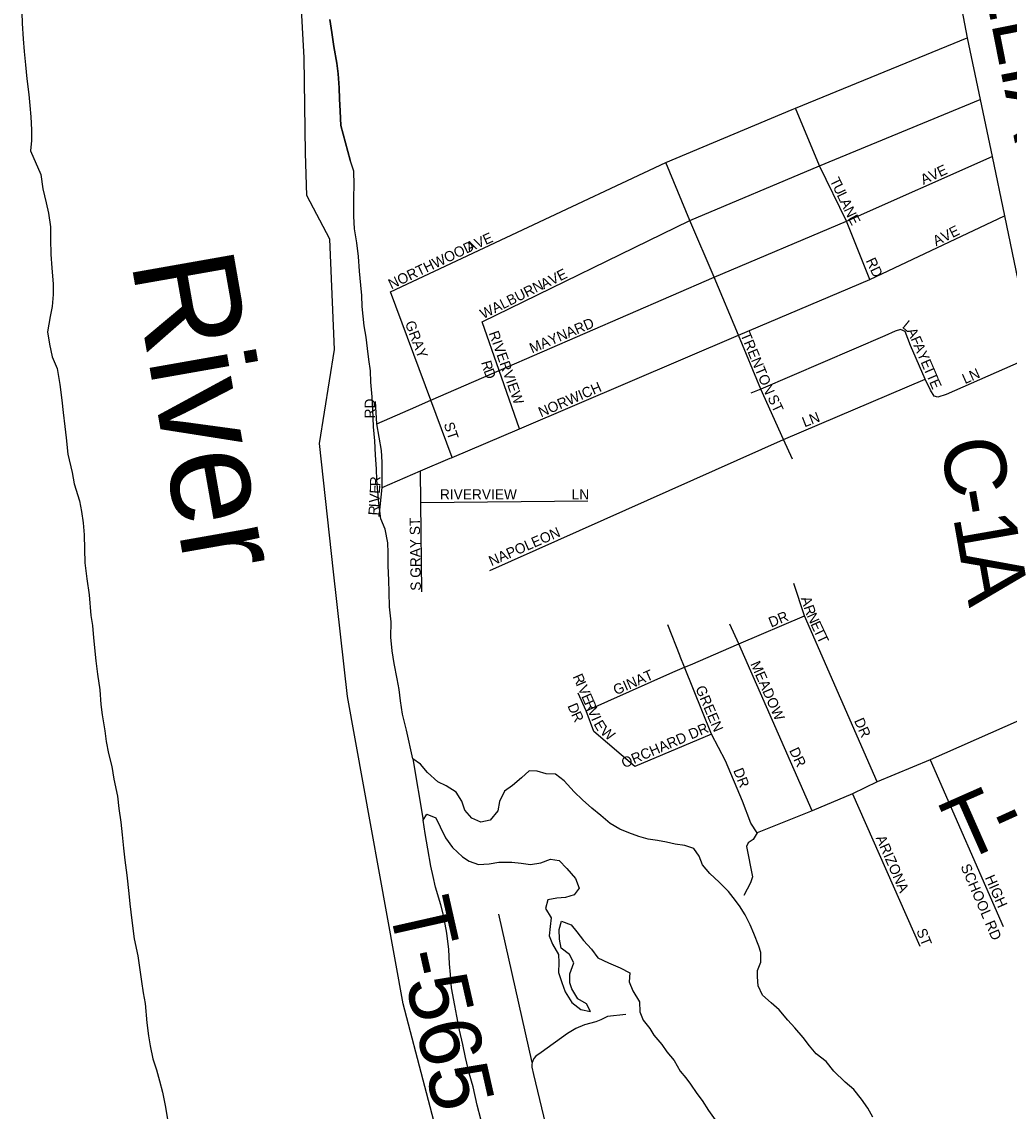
# Model space of a CAD drawing. Extents: x 1624196 to 2029251, y 146837 to 440034.
# Drawn here: x 1865322 to 1870139, y 223168 to 228483 of the extents above; entities that cross this region are included whole.
import ezdxf

# ---------------------------------------------------------------- set-up
doc = ezdxf.new("R2010")
doc.units = 0
for name, color, linetype in [('GM_X_County', 7, 'Continuous'), ('GM_X_County_Road', 7, 'Continuous'), ('GM_X_County_Road_Text', 7, 'Continuous'), ('GM_X_Major_River', 7, 'Continuous'), ('GM_X_Major_River_Text', 7, 'Continuous'), ('GM_X_Township', 7, 'Continuous'), ('GM_X_Township_Road', 7, 'Continuous'), ('GM_X_Township_Road_Text', 7, 'Continuous'), ('GM_X_Township_Subdivision', 7, 'Continuous'), ('GM_X_Township_Subdivision_Text', 7, 'Continuous')]:
    doc.layers.add(name, color=color, linetype=linetype)

msp = doc.modelspace()

# ---------------------------------------------------------------- linework, layer by layer
at = {"layer": 'GM_X_County'}
msp.add_lwpolyline([(1868956.8, 217512.7), (1868638.5, 218911.2), (1868232.1, 219758.7), (1868240.1, 219860.9), (1867949.8, 220532.1), (1867651.6, 221491.8), (1867393.3, 222884.3), (1867183.1, 223691.8), (1866910.8, 225190.5), (1866842.8, 225799.6), (1866774.7, 226424.7), (1866846.7, 226883.5), (1866824.7, 227422.5), (1866712.6, 227634.9), (1866705.8, 227842.5), (1866699.8, 228307.5), (1866657.8, 229078.2), (1866559.7, 229282.4), (1866457.7, 229772.9), (1866353.7, 230095.2), (1866417.7, 230521.6), (1866513.7, 230731.8), (1866563.7, 231274.4), (1866527.7, 232463.5)], dxfattribs=at)
at = {"layer": 'GM_X_County_Road'}
msp.add_lwpolyline([(1869763.2, 229303.8), (1869934.6, 228404.4), (1869997.4, 228103.3), (1870055.3, 227825.5), (1870115.7, 227535.9), (1870181.2, 227221.5), (1870231.5, 226954.2), (1870248.1, 226866.6), (1870354.7, 226302.8), (1870407.2, 226032.3), (1870452.8, 225744.5), (1870483.5, 225610.8), (1870514.2, 225428.5), (1870552.1, 225235.3), (1870606.6, 224963.7), (1870629.6, 224796.5), (1870709, 224246.7), (1870752.9, 223970.8), (1870773.8, 223690.7), (1870780.8, 223427.7), (1870792.7, 223044.3)], dxfattribs=at)
at = {"layer": 'GM_X_Major_River'}
msp.add_line((1867230.4, 224887.4), (1867280.4, 224588.1), dxfattribs=at)
for points in [[(1865321.9, 228528.4), (1865323.6, 228474.3), (1865329.2, 228400.2), (1865332.9, 228338.1), (1865340.6, 228272), (1865346.3, 228203.9), (1865355.9, 228127.8), (1865361.6, 228073.6), (1865365.3, 228019.6), (1865369, 227955.5), (1865368.8, 227903.4), (1865364.5, 227853.4)], [(1865321.9, 228528.4), (1865323.6, 228474.3), (1865329.2, 228400.2), (1865332.9, 228338.1), (1865340.6, 228272), (1865346.3, 228203.9), (1865355.9, 228127.8), (1865361.6, 228073.6), (1865365.3, 228019.6), (1865369, 227955.5), (1865368.8, 227903.4), (1865364.5, 227853.4)], [(1866924.3, 227807.2), (1866878.8, 227976.9), (1866875.1, 228047), (1866871.4, 228107.1), (1866869.7, 228161.2), (1866866, 228229.3), (1866858.3, 228281.4), (1866844.7, 228361.6), (1866835, 228429.7), (1866825.4, 228493.8)], [(1866825.4, 228493.8), (1866835, 228429.7), (1866844.7, 228361.6), (1866858.3, 228281.4), (1866866, 228229.3), (1866869.7, 228161.2), (1866871.4, 228107.1), (1866875.1, 228047), (1866878.8, 227976.9), (1866924.3, 227807.2)], [(1865364.5, 227853.4), (1865415.2, 227737.7), (1865424.8, 227667.5), (1865440.5, 227599.4), (1865452.2, 227549.2), (1865461.9, 227483), (1865461.6, 227422.9), (1865463.2, 227346.8), (1865468.9, 227282.7), (1865474.5, 227202.5), (1865474.3, 227152.4), (1865470, 227094.3), (1865459.7, 227044.3), (1865447.4, 226970.2), (1865457.1, 226910.1), (1865470.8, 226847.9), (1865494.5, 226791.7), (1865508.1, 226713.5), (1865517.7, 226637.3), (1865523.4, 226577.2), (1865531.1, 226509), (1865538.8, 226452.9), (1865546.4, 226372.7), (1865568, 226284.5), (1865577.7, 226228.4), (1865603.3, 226146.1), (1865613, 226094), (1865620.7, 226037.8), (1865626.4, 225979.7), (1865628.1, 225909.6), (1865629.8, 225843.4), (1865639.4, 225765.3), (1865651, 225687.1), (1865658.5, 225586.9), (1865666.2, 225536.8), (1865671.9, 225476.6), (1865683.4, 225364.4), (1865691.1, 225300.2), (1865702.7, 225224.1), (1865708.3, 225151.9), (1865714.1, 225101.8), (1865727.7, 225023.6), (1865733.4, 224971.5), (1865745.1, 224913.3), (1865760.8, 224849.1), (1865770.5, 224787), (1865788.1, 224704.8), (1865795.8, 224644.6), (1865805.5, 224578.5), (1865811.2, 224516.4), (1865818.8, 224450.2), (1865824.5, 224392.1), (1865834.2, 224319.9), (1865843.7, 224229.7), (1865849.5, 224179.6), (1865859.1, 224097.4), (1865870.7, 224009.2), (1865888.2, 223925), (1865895.9, 223868.9), (1865905.6, 223800.7), (1865913.3, 223744.6), (1865923.1, 223692.4), (1865932.6, 223598.2), (1865940.3, 223536.1), (1865948, 223486), (1865961.7, 223423.8), (1865979.5, 223369.6), (1865993.2, 223315.5), (1866008.9, 223261.3), (1866022.5, 223187.1), (1866032.2, 223127)], [(1867230.4, 224887.4), (1867198.6, 225027.2), (1867179, 225105.4), (1867169.3, 225169.6), (1867163.5, 225225.7), (1867153.8, 225277.8), (1867138.2, 225352), (1867128.5, 225414.2), (1867122.8, 225480.3), (1867123.2, 225554.4), (1867115.5, 225628.6), (1867113.9, 225700.7), (1867112.2, 225758.8), (1867108.5, 225829), (1867108.8, 225891.1), (1867107.1, 225941.2), (1867095.4, 226007.3), (1867073.7, 226057.5), (1867064, 226133.7), (1867058.3, 226191.8), (1867054.6, 226245.9), (1867052.9, 226302), (1867047.2, 226368.2), (1867043.5, 226438.3), (1867037.9, 226506.5), (1867034.3, 226592.6), (1867030.6, 226652.8), (1867025, 226724.9), (1867023.2, 226779), (1867015.5, 226835.1), (1867007.8, 226889.3), (1867002, 226943.4), (1866992.3, 226999.5), (1866982.8, 227093.7), (1866981, 227147.8), (1866975.3, 227197.9), (1866969.6, 227266.1), (1866964, 227338.2), (1866956.3, 227404.4), (1866944.7, 227472.6), (1866941, 227534.7), (1866941.4, 227624.8), (1866943.7, 227686.9), (1866942, 227753.1), (1866924.3, 227807.2)], [(1869473.3, 223138.4), (1869449.6, 223182.6), (1869417.9, 223226.8), (1869380.3, 223273.1), (1869338.6, 223309.4), (1869283, 223363.8), (1869245.3, 223410.1), (1869197.7, 223448.4), (1869164, 223486.7), (1869134.2, 223526.9), (1869092.6, 223575.2), (1869058.9, 223611.5), (1869017.3, 223661.8), (1868977.6, 223696.1), (1868935.9, 223734.4), (1868914.2, 223778.6), (1868910.4, 223822.7), (1868910.6, 223854.7), (1868926.9, 223894.7), (1868927.2, 223942.7), (1868917.4, 223972.8), (1868893.8, 224035), (1868876.1, 224077.2), (1868850.4, 224125.4), (1868822.7, 224169.7), (1868793, 224209.9), (1868769.2, 224240.1), (1868723.6, 224284.4), (1868677.9, 224326.7), (1868642.3, 224369), (1868626.5, 224411.2), (1868600.8, 224449.4), (1868557, 224463.6), (1868509.1, 224469.9), (1868467.2, 224480.2), (1868423.3, 224488.5), (1868377.5, 224494.8), (1868331.6, 224507.1), (1868283.8, 224525.4), (1868240, 224543.7), (1868192.3, 224572), (1868146.6, 224610.3), (1868102.9, 224646.6), (1868057.2, 224687), (1868017.5, 224725.2), (1867967.9, 224779.6), (1867926.2, 224811.9), (1867880.3, 224814.2), (1867836.4, 224826.5), (1867796.5, 224828.7), (1867760.3, 224794.9), (1867716.2, 224757.1), (1867676.1, 224729.3), (1867651.8, 224679.4), (1867643.6, 224633.4), (1867607.3, 224587.5), (1867561.4, 224577.8), (1867517.6, 224598.1), (1867483.8, 224636.4), (1867468.1, 224680.5), (1867440.5, 224724.7), (1867392.7, 224755.1), (1867350.9, 224775.3), (1867301.3, 224819.7), (1867267.6, 224860), (1867230.4, 224887.4)], [(1867280.4, 224588.1), (1867298, 224617.5), (1867341.8, 224599.2), (1867363.5, 224555), (1867389.2, 224500.8), (1867422.8, 224454.5), (1867472.5, 224408.1), (1867504.3, 224387.9), (1867550.1, 224371.6), (1867602, 224375.3), (1867650, 224383), (1867711.9, 224382.6), (1867757.8, 224378.4), (1867803.7, 224372.1)], [(1867561, 223128.3), (1867543.4, 223196.5), (1867523.8, 223286.8), (1867504.2, 223352.9), (1867486.6, 223429.2), (1867472.9, 223493.3), (1867457.2, 223563.5), (1867443.6, 223631.7), (1867433.8, 223683.8), (1867418.3, 223770), (1867412.6, 223834.2), (1867408.8, 223886.3), (1867405.2, 223956.4), (1867395.6, 224036.6), (1867380, 224124.8), (1867366.3, 224175), (1867340.7, 224261.2), (1867329, 224313.4), (1867317.2, 224363.5), (1867303.6, 224447.7), (1867290, 224521.9), (1867280.4, 224588.1)], [(1867803.7, 224372.1), (1867853.6, 224379.8), (1867901.7, 224397.5), (1867943.6, 224391.3), (1867981.2, 224351), (1868022.9, 224302.7), (1868040.6, 224256.5), (1868016.4, 224222.6), (1867974.4, 224210.8), (1867932.4, 224207.1), (1867888.5, 224199.3), (1867876.2, 224157.4), (1867903.9, 224111.1), (1867899.7, 224069.1), (1867895.4, 224023.1), (1867911.1, 223982.9), (1867940.8, 223932.7), (1867942.5, 223892.6), (1867940.2, 223844.6), (1867955.9, 223796.4), (1867973.6, 223750.2), (1868005.2, 223698), (1868048.9, 223663.7), (1868096.8, 223653.4), (1868077, 223691.5), (1868035.3, 223715.8), (1868005.6, 223764.1), (1867995.8, 223794.2), (1867996.1, 223838.2), (1868014.4, 223892.2), (1867994.7, 223932.4), (1867952.9, 223962.6), (1867945.2, 224006.8), (1867943.5, 224054.8), (1867955.7, 224094.8), (1868001.5, 224076.5), (1868029.3, 224042.3), (1868063, 224000), (1868100.6, 223957.7), (1868132.3, 223915.5), (1868184.1, 223891.1), (1868241.8, 223866.8), (1868287.6, 223842.5), (1868285.3, 223798.4), (1868303, 223754.3), (1868334.7, 223702), (1868336.4, 223651.9), (1868354.1, 223611.8), (1868385.8, 223571.5), (1868405.6, 223539.4), (1868445.2, 223493.1), (1868468.9, 223456.9), (1868504.6, 223414.6), (1868534.2, 223362.4), (1868562, 223330.1), (1868583.8, 223300), (1868615.4, 223253.7), (1868641.2, 223219.5), (1868672.8, 223171.3), (1868704.5, 223125)]]:
    msp.add_lwpolyline(points, dxfattribs=at)
at = {"layer": 'GM_X_Township'}
msp.add_lwpolyline([(1868956.8, 217512.7), (1868638.5, 218911.2), (1868232.1, 219758.7), (1868240.1, 219860.9), (1867949.8, 220532.1), (1867651.6, 221491.8), (1867393.3, 222884.3), (1867183.1, 223691.8), (1866910.8, 225190.5), (1866842.8, 225799.6), (1866774.7, 226424.7), (1866846.7, 226883.5), (1866824.7, 227422.5), (1866712.6, 227634.9), (1866705.8, 227842.5), (1866699.8, 228307.5), (1866657.8, 229078.2), (1866559.7, 229282.4), (1866457.7, 229772.9), (1866353.7, 230095.2), (1866417.7, 230521.6), (1866513.7, 230731.8), (1866563.7, 231274.4), (1866527.7, 232463.5)], dxfattribs=at)
at = {"layer": 'GM_X_Township_Road'}
for points in [[(1870552.1, 225235.3), (1869753.5, 224881.2), (1869495.5, 224775.1), (1869375.3, 224716.6), (1869177.4, 224633.4), (1868909.4, 224525.9), (1868889.2, 224493.8), (1868865.4, 224476.4), (1868858, 224459), (1868886, 224310.8), (1868877.5, 224282.4), (1868844.8, 224219.9)], [(1867812.3, 223405.7), (1867649.7, 224129.6)], [(1868268.3, 223638.7), (1868178.7, 223629.9), (1868147.2, 223613.1), (1868121.7, 223604.3), (1868066.6, 223589.5), (1868024.3, 223571.8), (1867984.9, 223547.2), (1867856, 223454.7), (1867829.8, 223435.5), (1867819.7, 223424.2), (1867812.3, 223405.7), (1867809.4, 223395.5), (1867809.8, 223382.9), (1867817.7, 223346.4), (1868176.7, 221855.1)]]:
    msp.add_lwpolyline(points, dxfattribs=at)
at = {"layer": 'GM_X_Township_Subdivision'}
for points in [[(1869080.8, 228054.9), (1869095.7, 228061.2), (1869934.6, 228404.4)], [(1867567.6, 227019.6), (1868580.7, 227513.8), (1869212.9, 227780.6), (1869997.4, 228103.3)], [(1867121.4, 227164.4), (1868463.5, 227796), (1869080.8, 228054.9)], [(1869459.6, 227225.5), (1869345.5, 227509.2), (1869212.9, 227780.6), (1869095.7, 228061.2)], [(1867247.2, 226605.9), (1867317.6, 226636.5), (1867650.8, 226781.2), (1868698.9, 227236.4), (1869345.5, 227509.2), (1870055.3, 227825.5)], [(1869081.9, 226349.6), (1869038.7, 226445.2), (1868927.7, 226690.4), (1868818.9, 226954.6), (1868698.9, 227236.4), (1868580.7, 227513.8), (1868463.5, 227796)], [(1867418.1, 226355.6), (1867421.5, 226357.1), (1867749.8, 226497.2), (1868818.9, 226954.6), (1869459.6, 227225.5), (1870115.7, 227535.9)], [(1867421.5, 226357.1), (1867317.6, 226636.5), (1867121.4, 227164.4)], [(1867749.8, 226497.2), (1867650.8, 226781.2), (1867567.6, 227019.6)], [(1870248.1, 226866.6), (1870226, 226847.7), (1870196.7, 226826.1), (1869831.3, 226664.2), (1869791.2, 226651.9), (1869772.7, 226656.5), (1869755.7, 226685.8), (1869729.5, 226739.7), (1869657, 226903.2), (1869630.8, 226971), (1869609.2, 226981.8), (1869583, 226972.6), (1869532.1, 226951), (1868927.7, 226690.4), (1868878.3, 226670.3)], [(1867604.9, 225806.3), (1869038.7, 226445.2), (1869729.5, 226739.7)], [(1867065.6, 226068.7), (1867079.6, 226211.1), (1867080.7, 226333.4), (1867077.5, 226390.5), (1867053.5, 226521.8), (1867047.5, 226630.1)], [(1867053.5, 226521.8), (1867244.9, 226604.9), (1867247.2, 226605.9)], [(1867079.6, 226211.1), (1867267, 226291.1), (1867412, 226353), (1867418.1, 226355.6)], [(1867273.3, 225700.8), (1867268.6, 226137.9), (1867267, 226291.1)], [(1867268.6, 226137.9), (1868083.2, 226145)], [(1869495.5, 224775.1), (1869140.8, 225585.2), (1869087.6, 225742.2)], [(1868583.8, 225345.9), (1868819.4, 225447.1), (1869140.8, 225585.2)], [(1868533.9, 225386.2), (1868533.1, 225388.2), (1868473.2, 225540.5)], [(1869177.4, 224633.4), (1868819.4, 225447.1), (1868776.9, 225543.5)], [(1868909.4, 224525.9), (1868879.1, 224573.6), (1868838.7, 224680.6), (1868754.8, 224876.9), (1868687.2, 225007.9), (1868555.2, 225333.7), (1868533.9, 225386.2)], [(1868075.4, 225121.4), (1868498.7, 225309.4), (1868555.2, 225333.7), (1868583.8, 225345.9)], [(1868312, 224849.4), (1868112.4, 225020.2), (1868075.4, 225121.4), (1868035.9, 225207.8)], [(1868687.2, 225007.9), (1868312, 224849.4)], [(1869753.5, 224881.2), (1870109.1, 224068.7)], [(1869375.3, 224716.6), (1869702.5, 223972.8)]]:
    msp.add_lwpolyline(points, dxfattribs=at)

# ---------------------------------------------------------------- texts
at = {"layer": 'GM_X_County_Road_Text'}
for s, rotation, p in [('GALLIA', 281.235, (1869893.5, 229266.9)), ('C', 279.9359, (1869800.9, 226431.4)), ('-', 279.9358, (1869843.5, 226188.7)), ('1', 279.9662, (1869864.8, 226067.2)), ('A', 280.1827, (1869896.9, 225883.9))]:
    msp.add_text(s, height=300, rotation=rotation, dxfattribs=at).set_placement(p)
at = {"layer": 'GM_X_Major_River_Text'}
msp.add_text('River', height=499.93, rotation=280.0024, dxfattribs=at).set_placement((1865854, 227313.7))
at = {"layer": 'GM_X_Township_Road_Text'}
for s, rotation, p in [('T', 23.8559, (1869907.6, 224380.2)), ('-', 24.3406, (1870115.3, 224472.1)), ('T-565', 282.7416, (1867109.3, 224171.3))]:
    msp.add_text(s, height=300, rotation=rotation, dxfattribs=at).set_placement(p)
at = {"layer": 'GM_X_Township_Subdivision_Text'}
for s, rotation, p in [('AVE', 24.7762, (1869720.8, 227687.1)), ('T', 295.6243, (1869262.5, 227708.9)), ('U', 295.6357, (1869277.7, 227677.2)), ('L', 295.6511, (1869296.7, 227637.5)), ('A', 295.6316, (1869312, 227605.8)), ('N', 295.6316, (1869331, 227566.1)), ('E', 298.0871, (1869351.1, 227524.4)), ('AVE', 26.5684, (1869782.2, 227387.7)), ('AVE', 23.9606, (1867503.4, 227357.1)), ('NORTHWOOD', 25.4368, (1867124.7, 227176.6)), ('RD', 295.1993, (1869438.5, 227317.3)), ('AVE', 26.565, (1867868.2, 227176.6)), ('WALBURN', 26.5636, (1867573.3, 227031.4)), ('GRAY', 290.7251, (1867190.4, 227013)), ('MAYNARD', 22.9892, (1867811.5, 226864.4)), ('L', 320.7961, (1869613.6, 226992.3)), ('RIVERVIEW', 289.6004, (1867599.7, 226964.2)), ('TRENTON', 292.6182, (1868827, 226956.1)), ('A', 297.3616, (1869637.4, 226974.2)), ('F', 293.3134, (1869657.3, 226936)), ('A', 293.3325, (1869671.2, 226903.7)), ('Y', 293.3278, (1869688.6, 226863.2)), ('R', 286.1456, (1867562, 226821.7)), ('E', 293.3428, (1869706.1, 226822.8)), ('T', 293.3134, (1869720, 226790.5)), ('LN', 23.9591, (1869923.4, 226714.5)), ('D', 290.394, (1867574.3, 226779.9)), ('T', 293.3428, (1869733.9, 226758.2)), ('E', 293.6595, (1869748, 226725.6)), ('NORWICH', 23.429, (1867855.4, 226551.9)), ('RD', 90, (1867044.6, 226547.7)), ('ST', 295.0149, (1868958.9, 226648.5)), ('ST', 288.4393, (1867379.7, 226519.9)), ('LN', 21.2487, (1869140.6, 226503.7)), ('R', 89.5542, (1867070.7, 226216.7)), ('E', 87.3585, (1867069, 226179.5)), ('V', 86.3446, (1867066.1, 226134.6)), ('RIVERVIEW', 0, (1867362, 226152.3)), ('LN', 0, (1868004.4, 226152.3)), ('R', 86.3547, (1867062.2, 226073.1)), ('I', 86.3255, (1867064.7, 226112.6)), ('S GRAY ST', 90.818, (1867268.9, 225707.2)), ('NAPOLEON', 23.4988, (1867613.4, 225825.9)), ('A', 287.6781, (1869122, 225670.5)), ('R', 288.6858, (1869135.6, 225627.6)), ('DR', 22.3775, (1868977.6, 225526.8)), ('N', 294.0398, (1869150.2, 225585.4)), ('E', 295.2036, (1869168.5, 225544.2)), ('T', 295.2233, (1869183.5, 225512.3)), ('T', 295.2026, (1869198.5, 225480.5)), ('MEADOW', 293.7828, (1868875.4, 225350.3)), ('GINAT', 23.5517, (1868220.6, 225196.7)), ('R', 293.5605, (1868008.6, 225288.6)), ('I', 293.5631, (1868024.4, 225252.3)), ('V', 293.543, (1868033.2, 225232.2)), ('E', 293.5524, (1868050.8, 225191.8)), ('GREEN', 293.1961, (1868607, 225231.4)), ('D', 292.8973, (1867982.9, 225145.8)), ('R', 293.554, (1868064.9, 225159.6)), ('R', 294.9042, (1868000.8, 225103.5)), ('V', 293.5631, (1868080.7, 225123.3)), ('I', 293.523, (1868098.3, 225082.9)), ('E', 300.4757, (1868110, 225057)), ('W', 321.3808, (1868140.6, 225011.9)), ('ORCHARD DR', 23.1983, (1868260.3, 224840.4)), ('DR', 293.9591, (1869381.2, 225073.1)), ('DR', 295.1993, (1869064.5, 224928.1)), ('DR', 291.2508, (1868791.9, 224830.7)), ('ARIZONA', 293.6837, (1869487, 224501.1)), ('SCHOOL RD', 293.2938, (1869900.8, 224361.4)), ('HIGH', 293.6283, (1870019.4, 224307.5)), ('ST', 291.8014, (1869685.1, 224047.6))]:
    msp.add_text(s, height=50, rotation=rotation, dxfattribs=at).set_placement(p)

doc.saveas('drawing.dxf')
